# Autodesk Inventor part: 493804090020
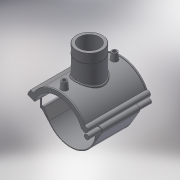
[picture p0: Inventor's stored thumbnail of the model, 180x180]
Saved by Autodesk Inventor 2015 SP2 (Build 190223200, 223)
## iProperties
Created: 2017-07
Part Number: 493804090020
Material: Generic
Description: PLASSON TRANSITION SADDLE 90-2"
Document SubType Name: Modeling
Designer: KIM
Density: 1 g/cm^3
Appearance: Default
Author: KIM
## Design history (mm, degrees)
derived "493804.ipt"
feature "Solid1::493804.ipt"
tag "TaggingFeature1"
body "Solid1"
other parameters: "d1" = 108, "d2" = 142, "d3" = 22.5, "d4" = 176, "d5" = 0, "d6" = 0.1, "d8" = 0, "d19" = 6, "d20" = 6, "d21" = 105.6, "d23" = 0, "d24" = 52.8, "d26" = 0, "d27" = 3, "d28" = 3, "d29" = 3, "d31" = 6, "d32" = 0, "d33" = 0, "d34" = 0.6, "d40" = 56.16, "d41" = 79.3184, "d43" = 0, "d45" = 0, "d48" = 73.6528, "d50" = 0, "d70" = 15, "d72" = 0, "d73" = 6, "d75" = 5, "d76" = 0, "d77" = 4.5, "d78" = 75, "d79" = 15, "d80" = 70.4, "d82" = 5 deg, "d84" = 4, "d85" = 14, "d86" = 0, "d87" = 3, "d88" = 0, "d89" = 1, "d90" = 1, "d91" = 140.8, "d92" = 0, "d93" = 0.5, "d94" = 47.36842, "d96" = 110.16, "d97" = 3.52, "d98" = 0, "d102" = 1.69968, "d103" = 56.656, "d104" = 45.6, "d105" = 0, "d106" = 45.3248, "d108" = 0, "d109" = -25.33333, "d111" = 0.5, "d112" = 0.5, "d113" = 0, "d114" = 0.5, "d117" = 0.56656, "d120" = 140 deg, "d121" = 24.228, "d122" = 20 deg, "d123" = 216, "d124" = 64.8, "d126" = 0, "d143" = 92.7, "d145" = 13.84615, "d149" = 1.35, "d150" = 15.23077, "d153" = 176, "d154" = 0, "d156" = 54, "d157" = 160 deg, "d159" = 3.6, "d161" = 1.35, "d162" = 105.6, "d163" = 0, "d164" = 45, "d167" = 9, "d168" = 52.68293, "d170" = 1.35, "d172" = 0, "d173" = 1, "d175" = 45, "d176" = 20 deg, "d177" = 6.3, "d178" = 18, "d180" = 0, "d183" = 7.2, "d184" = 5.04, "d185" = 57.2, "d186" = 57.2, "d187" = 54, "d188" = 5.4, "d189" = 6.3, "d190" = 0, "d191" = 64.8, "d193" = 3.6, "d194" = 4.4, "d195" = 90 deg, "d197" = 0, "d199" = 0, "B_" = 142, "H_" = 76, "L_" = 176, "d_t" = 6, "G_" = 56.656, "d148" = 1.35, "d160" = 1.35, "d169" = 1.35, "d192" = 3.6
